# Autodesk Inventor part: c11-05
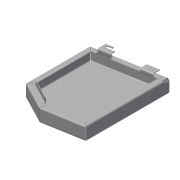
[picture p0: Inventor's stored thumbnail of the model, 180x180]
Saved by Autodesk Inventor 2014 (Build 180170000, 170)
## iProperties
Created: 2011-01
Part Number: c11-05
Material: Steel, Mild
Document SubType Name: Sheet Metal
Designer: Thom Tremblay
Density: 7.86 g/cm^3
Sheet Metal Rule: Steel - 16ga
Appearance: Steel
Author: Thom Tremblay
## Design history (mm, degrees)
node "Face1"
  sketch "Sketch1"
    geometry: L1 (0, 0)-(240, 0); L2 (240, 0)-(240, 300); L3 (240, 300)-(0, 300); L4 (0, 300)-(0, 0); L5 (140, 300)-(240, 229.979)
    constraints: 10 end point, 2 parallel, 2 point on line, 1 horizontal, 1 perpendicular
    dimensions: "d0" = 240 distance of L3.end L2.end; "d1" = 300 distance of L2.end L1.end; "d2" = 35 deg angle of L3 L5; "d3" = 100 distance from line of L2 L5.start
node "Flange1"
node "Flange2"
workplane "Work Plane1"
node "Flange3"
node "Face2"
  sketch "Sketch4"
    geometry: L1 (0, 15.428)-(214.889, 15.428) reference; L2 (25, 5.428)-(65, 5.428); L3 (65, 5.428)-(65, -4.572); L4 (65, -4.572)-(25, -4.572); L5 (25, -4.572)-(25, 5.428); 1 further point
    constraints: 8 end point, 2 parallel, 1 horizontal, 1 perpendicular
    dimensions: "d27" = 25 distance from line of L5 L1.start; "d28" = 10 distance of L4.end L2.start; "d29" = 40 distance of L3.end L4.end; "d50" = 10 distance between parallel lines of L1 L2
bend "Bend5" dims "d57" = 1.524 (= BendReliefWidth), "d58" = 0.762 (= BendReliefDepth), "d59" = 3.048 (= MinimumRemnant), "d60" = 3.048 (= BendRadius), "d61" = 3.048 (= BendRadius), "SeamGap" = 0.01, "Thickness" = 1.524 (derived)
node "Face3"
  sketch "Sketch5" dims "GapSize" = 0.762 (= 0.5 x Thickness)
    geometry: L1 (0, 15.428)-(214.889, 15.428) reference; L2 (160, 5.428)-(200, 5.428); L3 (200, 5.428)-(200, -18.572); L4 (160, -4.572)-(160, 5.428); L5 (200, -18.572)-(175, -18.572); L6 (175, -18.572)-(175, -12.572); L7 (175, -12.572)-(187, -12.572); L8 (187, -4.572)-(160, -4.572); A1 r 4 centre (187, -8.572) between (187, -12.572) and (187, -4.572); 1 further point
    constraints: 14 end point, 3 parallel, 3 perpendicular, 2 point on circle, 2 tangent, 1 centre point, 1 horizontal
    dimensions: "d30" = 10 distance of L4.start L2.start (= d28); "d32" = 160 distance from line of L1.start L4; "d51" = 10 distance between parallel lines of L1 L2; "d52" = 40 distance between parallel lines of L3 L4; "d53" = 25 distance of L3.end L5.end; "d54" = 12 distance from line of A1.centre L6; "d55" = 4 radius of A1; "d56" = 24 distance of L2.end L3.end
body "Solid1"
face "Plate1" dims "Thickness" = 1.524 (derived)
sketch "Sketch2"
  geometry: L1 through (-150, 0) direction (1, 0); L2 through (0, 20) direction (0, 1); L3 (0, 40)-(-300, 40); L4 (-300, 40)-(-300, 0)
  constraints: 6 end point, 1 horizontal, 1 perpendicular, 1 vertical
face "Plate2" dims "d5" = 1.524 (= BendReliefWidth), "d6" = 0.762 (= BendReliefDepth), "d7" = 3.048 (= MinimumRemnant), "d8" = 3.048 (= BendRadius), "d9" = 40, "d10" = 90 deg, "d11" = 3.048 (= BendRadius), "d12" = 6.096 (= CornerReliefSize), "d13" = 0.762 (= GapSize), "d14" = 3.048 (= JacobiRadiusSize), "SeamGap" = 0.01, "Thickness" = 1.524 (derived)
bend "Bend1" dims "d5" = 1.524 (= BendReliefWidth), "d6" = 0.762 (= BendReliefDepth), "d7" = 3.048 (= MinimumRemnant), "d8" = 3.048 (= BendRadius), "d9" = 40, "d10" = 90 deg, "d11" = 3.048 (= BendRadius), "SeamGap" = 0.01, "Thickness" = 1.524 (derived)
feature "Corner1" dims "d9" = 40, "d10" = 90 deg, "d12" = 6.096 (= CornerReliefSize), "d13" = 0.762 (= GapSize), "d14" = 3.048 (= JacobiRadiusSize)
sketch "Sketch3"
  geometry: L1 through (0, 147.937) direction (0, -1); L2 through (10, 0) direction (1, -4.12e-50); L3 (20, 0)-(20, 295.874); L4 (20, 295.874)-(0, 295.874)
  constraints: 6 end point, 1 horizontal, 1 perpendicular, 1 vertical
face "Plate3" dims "d15" = 1.524 (= BendReliefWidth), "d16" = 0.762 (= BendReliefDepth), "d17" = 3.048 (= MinimumRemnant), "d18" = 3.048 (= BendRadius), "d19" = 20, "d20" = 90 deg, "d21" = 3.048 (= BendRadius), "d22" = 6.096 (= CornerReliefSize), "d23" = 0.762 (= GapSize), "d24" = 3.048 (= JacobiRadiusSize), "d25" = 10, "SeamGap" = 0.01, "Thickness" = 1.524 (derived)
bend "Bend2" dims "d15" = 1.524 (= BendReliefWidth), "d16" = 0.762 (= BendReliefDepth), "d17" = 3.048 (= MinimumRemnant), "d18" = 3.048 (= BendRadius), "d19" = 20, "d20" = 90 deg, "d21" = 3.048 (= BendRadius), "SeamGap" = 0.01, "Thickness" = 1.524 (derived)
feature "Corner2" dims "d19" = 20, "d20" = 90 deg, "d22" = 6.096 (= CornerReliefSize), "d23" = 0.762 (= GapSize), "d24" = 3.048 (= JacobiRadiusSize)
face "Plate4" dims "d33" = 3.048 (= BendRadius), "d34" = 1.524 (= BendReliefWidth), "d36" = 3.048 (= MinimumRemnant), "Thickness" = 1.524 (derived)
bend "Bend3" dims "d33" = 3.048 (= BendRadius), "d34" = 1.524 (= BendReliefWidth), "d35" = 0.762 (= BendReliefDepth), "d36" = 3.048 (= MinimumRemnant), "d37" = 3.048 (= BendRadius), "SeamGap" = 0.01, "Thickness" = 1.524 (derived)
sketch "Sketch6"
  geometry: L1 (-94.531, 0)-(-10, 0); L2 (-10, 0)-(-10, 15); L3 (-10, 15)-(-94.531, 15); L4 (-94.531, 15)-(-94.531, 0)
  constraints: 8 end point
face "Plate5" dims "d38" = 1.524 (= BendReliefWidth), "d39" = 0.762 (= BendReliefDepth), "d40" = 3.048 (= MinimumRemnant), "d41" = 3.048 (= BendRadius), "d42" = 10, "d43" = 10, "d44" = 15, "d45" = 90 deg, "d46" = 3.048 (= BendRadius), "d47" = 6.096 (= CornerReliefSize), "d48" = 0.762 (= GapSize), "d49" = 3.048 (= JacobiRadiusSize), "SeamGap" = 0.01, "Thickness" = 1.524 (derived)
bend "Bend4" dims "d38" = 1.524 (= BendReliefWidth), "d39" = 0.762 (= BendReliefDepth), "d40" = 3.048 (= MinimumRemnant), "d41" = 3.048 (= BendRadius), "d44" = 15, "d45" = 90 deg, "d46" = 3.048 (= BendRadius), "SeamGap" = 0.01, "Thickness" = 1.524 (derived)
feature "Corner3" dims "d44" = 15, "d45" = 90 deg, "d47" = 6.096 (= CornerReliefSize), "d48" = 0.762 (= GapSize), "d49" = 3.048 (= JacobiRadiusSize)
face "Plate6" dims "d62" = 3.048 (= BendRadius), "d63" = 1.524 (= BendReliefWidth), "d65" = 3.048 (= MinimumRemnant), "Thickness" = 1.524 (derived)
bend "Bend6" dims "d62" = 3.048 (= BendRadius), "d63" = 1.524 (= BendReliefWidth), "d64" = 0.762 (= BendReliefDepth), "d65" = 3.048 (= MinimumRemnant), "d66" = 3.048 (= BendRadius), "SeamGap" = 0.01, "Thickness" = 1.524 (derived)
other parameters: "BendRadius" = 3.048 (= 2 x Thickness), "BendReliefWidth" = 1.524 (= Thickness), "BendReliefDepth" = 0.762 (= 0.5 x Thickness), "CornerReliefSize" = 6.096 (= 4 x Thickness), "MinimumRemnant" = 3.048 (= 2 x Thickness), "TransitionRadius" = 3.048 (= BendRadius), "JacobiRadiusSize" = 3.048 (= BendRadius), "d4" = 3.048 (= BendRadius)
